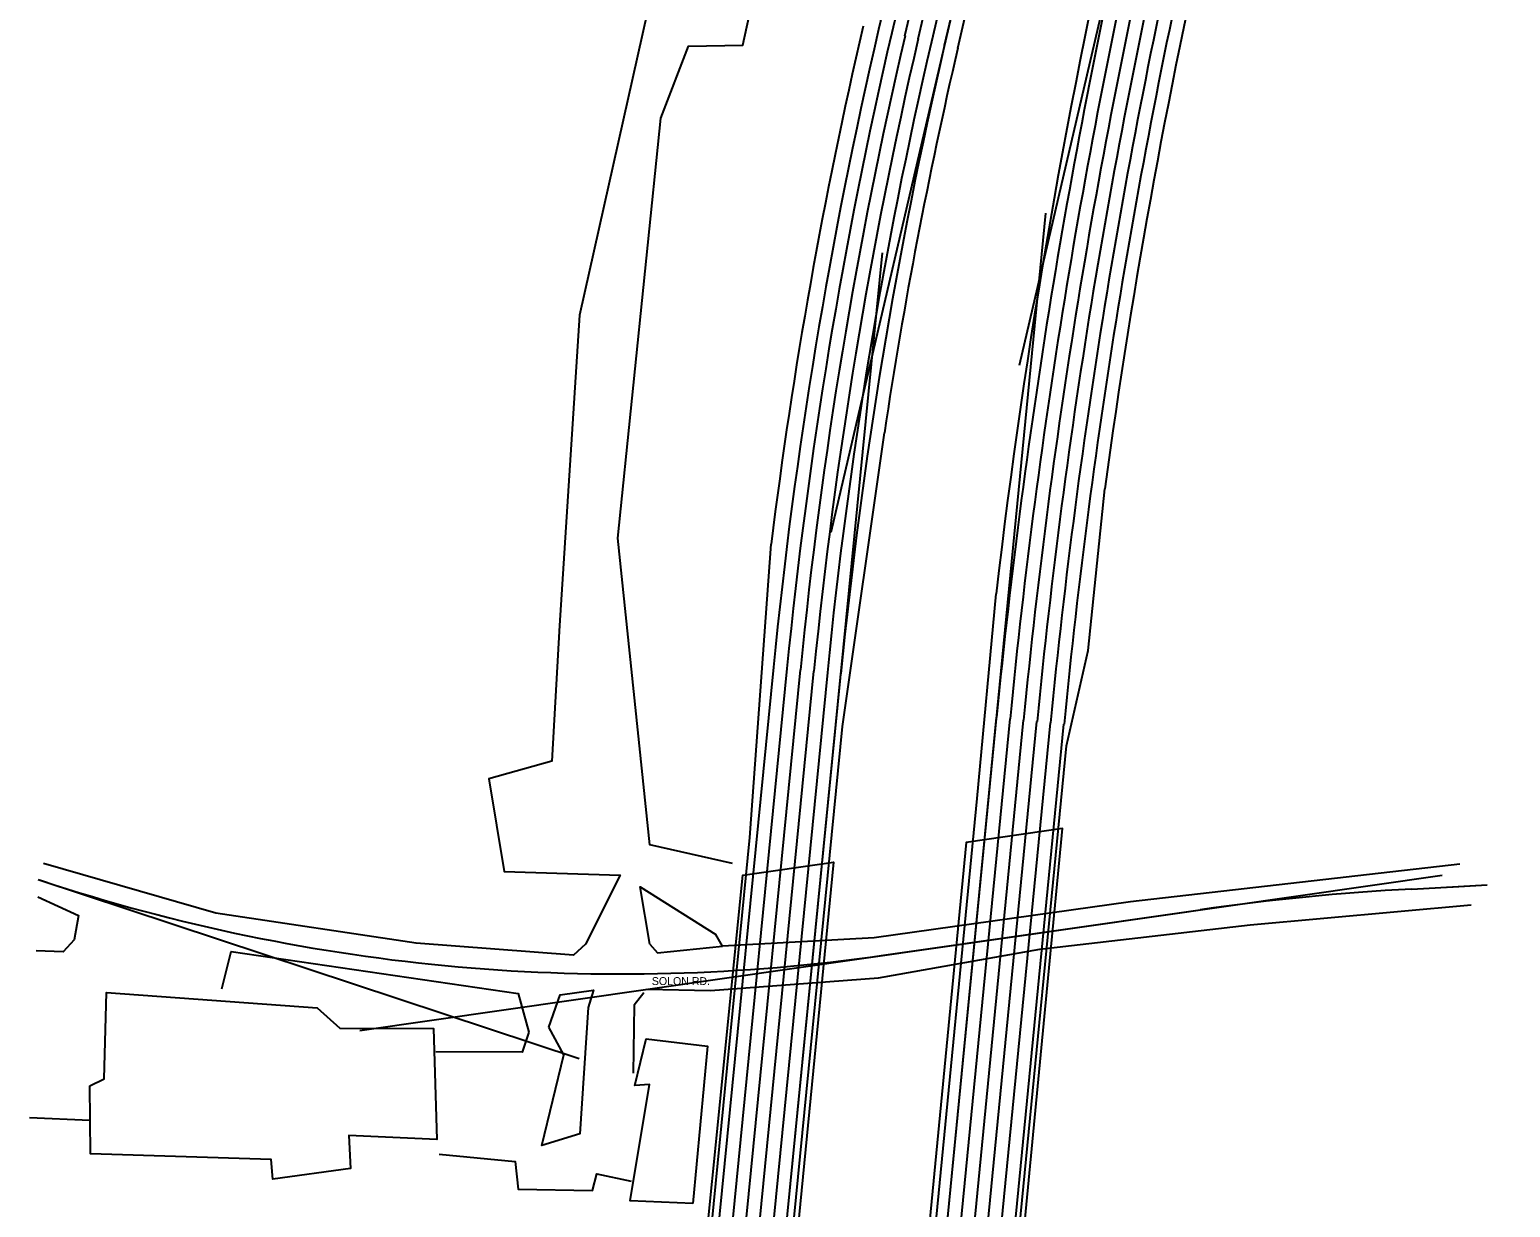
# Model space of a CAD drawing. Extents: x 227157 to 233208, y 434992 to 456232.
# Drawn here: x 228490 to 229801, y 450094 to 451136 of the extents above; entities that cross this region are included whole.
import ezdxf

# ---------------------------------------------------------------- set-up
doc = ezdxf.new("R2010")
doc.units = 0
for name, color, linetype in [('BD_X_Building', 7, 'Continuous'), ('BR_X_Slab_Object', 7, 'Continuous'), ('GE_X_Alignment', 7, 'Continuous'), ('PM_X_Edge_Line', 7, 'Continuous'), ('PM_X_Lane_Line', 7, 'Continuous'), ('PV_X_EOP', 7, 'Continuous'), ('SV_X_Text_Name', 7, 'Continuous')]:
    doc.layers.add(name, color=color, linetype=linetype)

msp = doc.modelspace()

# ---------------------------------------------------------------- linework, layer by layer
at = {"layer": 'BD_X_Building'}
for points in [[(228543.7, 450201.3), (228556.3, 450207.6), (228558.3, 450284), (228744.6, 450270.4), (228764.7, 450252.4), (228847.6, 450252.1), (228850.5, 450153.9), (228772.8, 450157.4), (228774.2, 450128), (228705.6, 450118.7), (228704, 450136), (228544.3, 450141.2)], [(229077.2, 450097.2), (229021.8, 450099.6), (229038.7, 450202.6), (229026, 450201.5), (229035.9, 450242.9), (229090.2, 450236.5)]]:
    msp.add_lwpolyline(points, close=True, dxfattribs=at)
at = {"layer": 'BR_X_Slab_Object'}
for points in [[(229212.1, 449307.6), (229296.9, 449307.3), (229404.3, 450429.2), (229319.1, 450416.6)], [(229095.5, 449309.3), (229013.6, 449309), (229121.5, 450387.8), (229201.6, 450399.2)]]:
    msp.add_lwpolyline(points, close=True, dxfattribs=at)
at = {"layer": 'GE_X_Alignment'}
for p, q in [((229199.7, 450691.4), (230466.2, 456134.6)), ((229366.4, 450839.2), (230553.2, 455944.3)), ((229216.7, 449201.7), (229389.5, 450973.9)), ((228999.7, 448451.5), (229245, 450938.7)), ((228782.6, 450250.3), (229740.4, 450387.9)), ((228497.9, 450383.9), (228976.5, 450225.5)), ((229744.9, 450377.2), (229780, 450379.1))]:
    msp.add_line(p, q, dxfattribs=at)
for centre, radius, start, end in [((235213.1, 449955.1), 5895, 166.9125, 174.43069), ((233519.3, 450140.9), 4332, 166.9016, 174.3687), ((229013.7, 451932.8), 1632.5, 251.6845, 278.1752), ((229824.4, 448281.5), 2096.9, 93.0372, 98.1752)]:
    msp.add_arc(centre, radius, start, end, dxfattribs=at)
at = {"layer": 'PM_X_Edge_Line'}
for p, q in [((229955.7, 454205.6), (229241.6, 451136.2)), ((229300, 451122.6), (230014.2, 454192)), ((229148.5, 450571.9), (229003.6, 449102.3)), ((229063.3, 449096.4), (229208.2, 450566)), ((229216.7, 449201.7), (229345.9, 450527.2)), ((229285.5, 449289.8), (229405.6, 450521.4)), ((228497.9, 450383.9), (228500.7, 450383)), ((229713.3, 450375.5), (229780, 450379.1)), ((229245.8, 450316.9), (229526.2, 450357.2))]:
    msp.add_line(p, q, dxfattribs=at)
for centre, radius, start, end in [((235213.1, 449955.1), 5895, 166.9125, 174.43069), ((235213.1, 449955.1), 5835, 166.9125, 174.43069), ((233519.3, 450140.9), 4392, 166.9016, 174.3687), ((233519.3, 450140.9), 4332, 166.9016, 174.3687), ((229013.7, 451932.8), 1632.5, 251.6845, 278.1752), ((229824.4, 448281.5), 2096.9, 93.0372, 98.1752)]:
    msp.add_arc(centre, radius, start, end, dxfattribs=at)
at = {"layer": 'PM_X_Lane_Line'}
for p, q in [((229967.4, 454202.9), (229253.3, 451133.5)), ((229264.9, 451130.8), (229979.1, 454200.2)), ((229276.6, 451128.1), (229990.8, 454197.5)), ((230002.5, 454194.7), (229288.3, 451125.4)), ((229160.4, 450570.7), (229015.5, 449101.1)), ((229039.4, 449098.8), (229184.3, 450568.3)), ((229092.7, 449761), (229172.4, 450569.5)), ((229196.3, 450567.2), (229051.4, 449097.6)), ((229237.7, 449294.3), (229357.9, 450526.1)), ((229249.7, 449293.1), (229369.8, 450524.9)), ((229261.6, 449291.9), (229381.7, 450523.7)), ((229273.6, 449290.8), (229393.7, 450522.6))]:
    msp.add_line(p, q, dxfattribs=at)
for centre, radius, start, end in [((235213.1, 449955.1), 5883, 166.9125, 174.43069), ((235213.1, 449955.1), 5871, 166.9125, 174.43069), ((235213.1, 449955.1), 5859, 166.9125, 174.43069), ((235213.1, 449955.1), 5847, 166.9125, 174.43069), ((233519.3, 450140.9), 4380, 166.9016, 174.3687), ((233519.3, 450140.9), 4368, 166.9016, 174.3687), ((233519.3, 450140.9), 4356, 166.9016, 174.3687), ((233519.3, 450140.9), 4344, 166.9016, 174.3687)]:
    msp.add_arc(centre, radius, start, end, dxfattribs=at)
at = {"layer": 'PV_X_EOP'}
for p, q in [((229311.7, 451119.9), (230025.9, 454189.3)), ((229209.7, 450519.5), (229246.7, 450779.2)), ((229427.1, 450586.5), (229441.8, 450729.7)), ((229127.6, 450421), (229146.5, 450680.9)), ((229328.9, 450455.6), (229345.6, 450636.9)), ((229407.8, 450502.2), (229427.1, 450586.5)), ((229091.7, 449323.4), (229209.7, 450519.5)), ((229292.8, 449322.7), (229407.8, 450502.2)), ((229216.9, 449307.7), (229328.9, 450455.6)), ((229019, 449319.3), (229127.6, 450421)), ((228543.7, 450170.5), (228490.3, 450173))]:
    msp.add_line(p, q, dxfattribs=at)
for points in [[(229112.3, 450398.2), (229039, 450414.5), (229010.7, 450686), (229048.8, 451057.8), (229073.2, 451121.7), (229121.4, 451122.6), (229160.9, 451303.7)], [(229045.3, 451189.5), (228976.9, 450883.4), (228959.1, 450608.7), (228952.5, 450488.7), (228896.6, 450473.1), (228910.3, 450391), (229013, 450387.9), (228982.2, 450326.6)], [(228982.2, 450326.6), (228971.7, 450317.1), (228832.4, 450327.7), (228655, 450354.2), (228502.5, 450398)], [(229755.8, 450397.4), (229464.5, 450364.3), (229237.7, 450332.2), (229103.4, 450324.9), (229097.5, 450335.3)], [(229039.2, 450326.8), (229030.7, 450377.3), (229097.5, 450335.3)], [(228497.5, 450368.5), (228533.5, 450352), (228529.8, 450330.6), (228520.1, 450319.9), (228496, 450320.8)], [(229036.6, 450286.8), (229092.7, 450285.6), (229241.5, 450296.9), (229384.2, 450322.3), (229570.3, 450343.7), (229766, 450361.6)], [(228660.5, 450287.2), (228668.6, 450320.2), (228922.6, 450283), (228932.2, 450248.7)], [(229039.2, 450326.8), (229045.8, 450319.1), (229103.4, 450324.9)], [(228949.7, 450253.2), (228959.7, 450281.8), (228989.3, 450286), (228984.6, 450270.7)], [(229033.9, 450283.5), (229025.3, 450272.6), (229024.5, 450212.6)], [(228984.6, 450270.7), (228977.2, 450158.9), (228943.5, 450148.5), (228963, 450228.6), (228949.7, 450253.2)], [(228932.2, 450248.7), (228926.1, 450231.1), (228849.9, 450231.3)], [(228852.6, 450140.8), (228920.1, 450134.4), (228922.6, 450109.9), (228988.3, 450108.7), (228992.2, 450123.4), (229022.5, 450116.9)]]:
    msp.add_lwpolyline(points, dxfattribs=at)
for centre, radius, start, end in [((235213.1, 449955.1), 5907, 166.9125, 173.37229), ((235213.1, 449955.1), 5823, 166.9125, 172.35625), ((233519.3, 450140.9), 4406, 166.9016, 172.9603), ((233519.3, 450140.9), 4320, 166.9016, 171.5029)]:
    msp.add_arc(centre, radius, start, end, dxfattribs=at)

# ---------------------------------------------------------------- texts
at = {"layer": 'SV_X_Text_Name'}
msp.add_text('SOLON RD.', height=7, dxfattribs=at).set_placement((229040.9, 450290.5))

doc.saveas('drawing.dxf')
